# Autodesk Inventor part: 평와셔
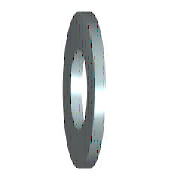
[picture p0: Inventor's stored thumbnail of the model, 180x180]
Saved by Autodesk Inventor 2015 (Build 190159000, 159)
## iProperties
IsCustomPart: 1
Created: 2012-02
Part Number: 평와셔
Material: 강철
Description: 평면 와셔 - 초대형 시리즈 - 제품 등급 C
Document SubType Name: Modeling
Standard: ISO 7094
Designer: mduedu
Standard Revision: Second edition 2000-06-01
Standards Organization: ISO
Language: ko-KR
Size Designation: ST 5 - 100 HV
Categories: <MemberInstance><Categories><Category DisplayName="조임쇠" InternalName="e4da775c-781d-43d5-af7c-5136215cf5a6" Mnemonic="FSTN"><Category DisplayName="와셔" InternalN
Density: 7.85 g/cm^3
Appearance: 강철
Author: mduedu
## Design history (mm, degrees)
sketch "스케치"
  geometry: C1 r 9 at (0, 0); C2 r 2.75 at (0, 0); 1 further point
  constraints: 2 centre point, 2 coincident
  dimensions: "d0" = 5.5 diameter of C2 (= SD1); "d1" = 18 diameter of C1 (= SD2)
extrude "본체" new body sketch "스케치" distance "d2" = 2 (= SD); taper "d3" = 0 deg
workaxis "Work Axis1"
workplane "Work Plane1"
body "Solid1"
other parameters: "SD1" = 5.5 [user parameter; used in 1 equation term], "SD2" = 18 [user parameter; used in 1 equation term], "SD" = 2 [user parameter; used in 1 equation term], "d4" = 0, "d5" = 0, "d6" = 0, "d7" = 0, "NND" = 5 [user parameter]
